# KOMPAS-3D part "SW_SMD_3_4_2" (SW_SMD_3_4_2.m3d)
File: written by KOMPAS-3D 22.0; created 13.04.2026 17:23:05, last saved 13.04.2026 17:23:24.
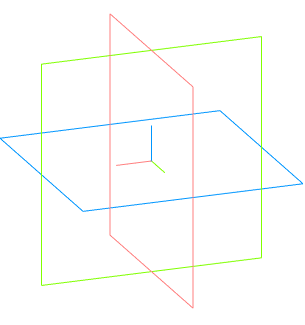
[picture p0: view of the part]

Document properties: Автор: Andrey; Полное имя файла: C:\Users\User1\Documents\Работа\Корпуса\Корпус Repka Pi 5\Конструкторская документация\3д модель\Repka_5_3D\SW_SMD_3_4_2.m3d

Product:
- Part/product: SW_SMD_3_4_2
    Комментарий: SW_SMD_3_4_2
